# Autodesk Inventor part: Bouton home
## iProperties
Created: 2010-07
Part Number: Bouton home
Document SubType Name: Modeling
Designer: eric
Density: 1 g/cm^3
Mass: 1.1e-05 g
Surface Area: 0.02242 cm^2
Volume: 1.1e-05 cm^3
Author: eric
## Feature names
1. Base1
